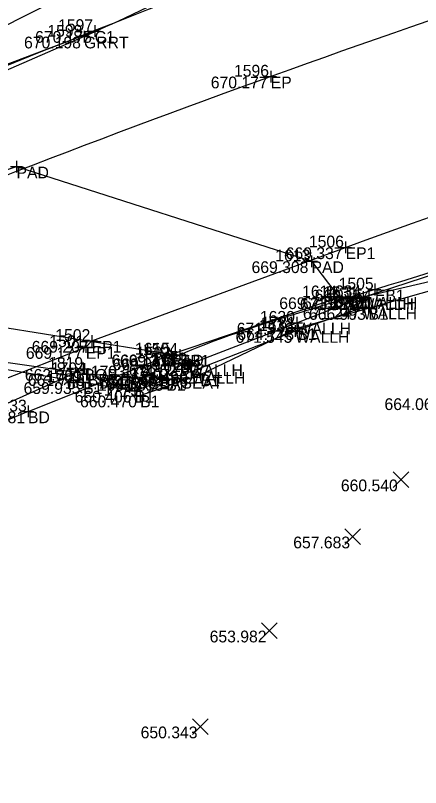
# Model space of a CAD drawing. Extents: x 2197382 to 2204062, y 634117 to 636522.
# Drawn here: x 2202998.7 to 2203033.1, y 635376.2 to 635441.9 of the extents above; entities that cross this region are included whole.
import ezdxf

# ---------------------------------------------------------------- set-up
doc = ezdxf.new("R2010")
doc.units = 0
for name, color, linetype in [('_CIVIL_CONSTRUCTION', 7, 'Continuous'), ('BR_P_Gen_Approach_Slab', 7, 'Continuous'), ('BR_X_SV_Beam_Seat', 7, 'Continuous'), ('BR_X_SV_Bottom_of_Beam', 7, 'Continuous'), ('BR_X_SV_Bottom_of_Beam_Text', 7, 'Continuous'), ('BR_X_SV_Deck_Top', 7, 'Continuous'), ('BR_X_SV_Deck_Top_Text', 7, 'Continuous'), ('BR_X_SV_Shot_Marker', 7, 'Continuous'), ('Default', 7, 'Continuous'), ('DR_X_Headwall', 7, 'Continuous'), ('GE_P_Alignment_100_Distances', 7, 'Continuous'), ('GE_X_Alignment', 7, 'Continuous'), ('PF_P_Grade_Line', 7, 'Continuous'), ('PV_X_Curb', 7, 'Continuous'), ('RD_X_GR_Rt', 7, 'Continuous'), ('RW_X_CL_100_Curve_Data', 7, 'Continuous'), ('SH_Border', 7, 'Continuous'), ('SH_Cut_Line', 7, 'Continuous'), ('SH_Data', 7, 'Continuous'), ('SH_Text', 7, 'Continuous')]:
    doc.layers.add(name, color=color, linetype=linetype)

msp = doc.modelspace()

# ---------------------------------------------------------------- linework, layer by layer
at = {"layer": '_CIVIL_CONSTRUCTION'}
for p, q in [((2203005.415, 635441.073), (2203005.415, 635440.073)), ((2203004.506, 635440.595), (2203004.506, 635439.595)), ((2203004.915, 635440.573), (2203005.915, 635440.573)), ((2203005.415, 635440.573), (2203005.415, 635440.573)), ((2203004.006, 635440.095), (2203005.006, 635440.095)), ((2203004.506, 635440.095), (2203004.506, 635440.095)), ((2203020.38, 635437.196), (2203020.38, 635436.196)), ((2203019.88, 635436.696), (2203020.88, 635436.696)), ((2203020.38, 635436.696), (2203020.38, 635436.696)), ((2202998.767, 635429.534), (2202998.767, 635428.534)), ((2202998.267, 635429.034), (2202999.267, 635429.034)), ((2202998.767, 635429.034), (2202998.767, 635429.034)), ((2203026.75, 635422.664), (2203026.75, 635421.664)), ((2203026.25, 635422.164), (2203027.25, 635422.164)), ((2203026.75, 635422.164), (2203026.75, 635422.164)), ((2203023.848, 635421.478), (2203023.848, 635420.478)), ((2203023.348, 635420.978), (2203024.348, 635420.978)), ((2203023.848, 635420.978), (2203023.848, 635420.978)), ((2203029.243, 635419.076), (2203029.243, 635418.076)), ((2203026.189, 635418.412), (2203026.189, 635417.412)), ((2203027.939, 635418.339), (2203027.939, 635417.339)), ((2203028.231, 635418.431), (2203028.231, 635417.431)), ((2203028.743, 635418.576), (2203029.743, 635418.576)), ((2203029.243, 635418.576), (2203029.243, 635418.576)), ((2203025.689, 635417.912), (2203026.689, 635417.912)), ((2203026.189, 635417.912), (2203026.189, 635417.912)), ((2203027.439, 635417.839), (2203028.439, 635417.839)), ((2203027.731, 635417.931), (2203028.731, 635417.931)), ((2203027.939, 635417.839), (2203027.939, 635417.839)), ((2203028.214, 635417.55), (2203028.214, 635416.55)), ((2203028.231, 635417.931), (2203028.231, 635417.931)), ((2203028.695, 635417.498), (2203028.695, 635416.498)), ((2203027.714, 635417.05), (2203028.714, 635417.05)), ((2203028.195, 635416.998), (2203029.195, 635416.998)), ((2203028.214, 635417.05), (2203028.214, 635417.05)), ((2203028.695, 635416.998), (2203028.695, 635416.998)), ((2203022.591, 635416.25), (2203022.591, 635415.25)), ((2203022.091, 635415.75), (2203023.091, 635415.75)), ((2203022.461, 635415.543), (2203022.461, 635414.543)), ((2203022.591, 635415.75), (2203022.591, 635415.75)), ((2203022.64, 635415.776), (2203022.64, 635414.776)), ((2203005.156, 635414.704), (2203005.156, 635413.704)), ((2203021.961, 635415.043), (2203022.961, 635415.043)), ((2203022.14, 635415.276), (2203023.14, 635415.276)), ((2203022.461, 635415.043), (2203022.461, 635415.043)), ((2203022.64, 635415.276), (2203022.64, 635415.276)), ((2203004.654, 635414.181), (2203004.654, 635413.181)), ((2203004.656, 635414.204), (2203005.656, 635414.204)), ((2203005.156, 635414.204), (2203005.156, 635414.204)), ((2203004.154, 635413.681), (2203005.154, 635413.681)), ((2203004.654, 635413.681), (2203004.654, 635413.681)), ((2203011.925, 635413.541), (2203011.925, 635412.541)), ((2203012.655, 635413.513), (2203012.655, 635412.513)), ((2203011.425, 635413.041), (2203012.425, 635413.041)), ((2203011.925, 635413.041), (2203011.925, 635413.041)), ((2203012.015, 635413.219), (2203012.015, 635412.219)), ((2203012.155, 635413.013), (2203013.155, 635413.013)), ((2203012.655, 635413.013), (2203012.655, 635413.013)), ((2203004.554, 635412.314), (2203004.554, 635411.314)), ((2203011.515, 635412.719), (2203012.515, 635412.719)), ((2203012.015, 635412.719), (2203012.015, 635412.719)), ((2203012.897, 635412.206), (2203013.897, 635412.206)), ((2203013.397, 635412.706), (2203013.397, 635411.706)), ((2203013.397, 635412.206), (2203013.397, 635412.206)), ((2203004.054, 635411.814), (2203005.054, 635411.814)), ((2203004.554, 635411.814), (2203004.554, 635411.814)), ((2203011.512, 635411.463), (2203011.512, 635410.463)), ((2203013.114, 635411.565), (2203014.114, 635411.565)), ((2203013.614, 635412.065), (2203013.614, 635411.065)), ((2203013.614, 635411.565), (2203013.614, 635411.565)), ((2203014.402, 635411.844), (2203014.402, 635410.844)), ((2203004.435, 635411.191), (2203004.435, 635410.191)), ((2203011.012, 635410.963), (2203012.012, 635410.963)), ((2203011.512, 635410.963), (2203011.512, 635410.963)), ((2203013.902, 635411.344), (2203014.902, 635411.344)), ((2203014.402, 635411.344), (2203014.402, 635411.344)), ((2203003.935, 635410.691), (2203004.935, 635410.691)), ((2203004.435, 635410.691), (2203004.435, 635410.691)), ((2203008.816, 635410.46), (2203008.816, 635409.46)), ((2203008.316, 635409.96), (2203009.316, 635409.96)), ((2203008.78, 635409.551), (2203009.78, 635409.551)), ((2203008.816, 635409.96), (2203008.816, 635409.96)), ((2203009.28, 635410.051), (2203009.28, 635409.051)), ((2203009.28, 635409.551), (2203009.28, 635409.551)), ((2202999.242, 635408.201), (2203000.242, 635408.201)), ((2202999.742, 635408.701), (2202999.742, 635407.701)), ((2202999.742, 635408.201), (2202999.742, 635408.201))]:
    msp.add_line(p, q, dxfattribs=at)
at = {"layer": 'BR_P_Gen_Approach_Slab'}
msp.add_lwpolyline([(2202961.037, 635421.211), (2202992.345, 635433.447), (2202995.802, 635428.045), (2202998.767, 635429.034), (2203023.848, 635420.978), (2203026.189, 635417.912), (2203011.925, 635413.041)], close=True, dxfattribs=at)
at = {"layer": 'BR_X_SV_Bottom_of_Beam'}
msp.add_lwpolyline([(2203004.554, 635411.814), (2202987.707, 635404.283), (2202970.923, 635396.976), (2202953.857, 635390.063), (2202937.114, 635382.149)], dxfattribs=at)
at = {"layer": 'BR_X_SV_Deck_Top'}
for q in [(2203011.925, 635413.041), (2202923.181, 635376.197)]:
    msp.add_line((2202999.742, 635408.201), q, dxfattribs=at)
at = {"layer": 'BR_X_SV_Shot_Marker'}
for p, q in [((2203004.829, 635411.876), (2203004.829, 635410.876)), ((2203008.169, 635411.593), (2203008.169, 635410.593)), ((2203010.93, 635411.648), (2203010.93, 635410.648)), ((2203004.329, 635411.376), (2203005.329, 635411.376)), ((2203004.829, 635411.376), (2203004.829, 635411.376)), ((2203007.669, 635411.093), (2203008.669, 635411.093)), ((2203008.169, 635411.093), (2203008.169, 635411.093)), ((2203010.43, 635411.148), (2203011.43, 635411.148)), ((2203010.93, 635411.148), (2203010.93, 635411.148))]:
    msp.add_line(p, q, dxfattribs=at)
at = {"layer": 'Default'}
msp.add_lwpolyline([(2203010.93, 635411.148), (2203008.169, 635411.093), (2203004.829, 635411.376), (2202991.262, 635413.289), (2202991.069, 635413.101), (2202976.24, 635415.493), (2202976.127, 635415.526), (2202961.376, 635417.927), (2202961.247, 635417.936), (2202955.257, 635418.901), (2202955.015, 635419.365), (2202958.181, 635420.848)], dxfattribs=at)
at = {"layer": 'DR_X_Headwall'}
for points in [[(2203028.231, 635417.931), (2203039.816, 635421.698), (2203041.345, 635421.885), (2203041.59, 635421.173), (2203040.06, 635420.674)], [(2203013.614, 635411.565), (2203013.397, 635412.206), (2203022.591, 635415.75), (2203027.939, 635417.839), (2203028.214, 635417.05), (2203022.461, 635415.043)]]:
    msp.add_lwpolyline(points, close=True, dxfattribs=at)
at = {"layer": 'GE_P_Alignment_100_Distances'}
for p, q in [((2203005.156, 635414.204), (2203026.75, 635422.164)), ((2203004.654, 635413.681), (2203005.156, 635414.204)), ((2202973.99, 635401.58), (2203004.654, 635413.681))]:
    msp.add_line(p, q, dxfattribs=at)
for points in [[(2203509.325, 635523.639), (2203492.709, 635523.635), (2203459.449, 635522.771), (2203409.618, 635520.273), (2203359.906, 635516.085), (2203310.487, 635509.396), (2203261.113, 635501.99), (2203212.046, 635492.428), (2203163.488, 635480.651), (2203115.287, 635467.725), (2203067.636, 635452.84), (2203020.399, 635437.148), (2202989.518, 635425.126), (2202974.268, 635418.841)], [(2203026.75, 635422.164), (2203041.875, 635427.739), (2203072.979, 635437.38), (2203119.81, 635452.49), (2203167.644, 635464.687), (2203215.6, 635476.186), (2203263.862, 635485.772), (2203312.689, 635493.217), (2203361.79, 635499.124), (2203411.114, 635503.522), (2203460.348, 635505.942), (2203493.138, 635506.785), (2203509.372, 635506.858)]]:
    msp.add_open_spline(points, degree=3, dxfattribs=at)
at = {"layer": 'GE_X_Alignment'}
msp.add_line((2203012.015, 635412.719), (2203012.655, 635413.013), dxfattribs=at)
for points in [[(2203509.052, 635533.635), (2203492.463, 635533.632), (2203459.115, 635532.727), (2203409.096, 635530.449), (2203358.983, 635525.688), (2203309.163, 635519.456), (2203259.639, 635511.376), (2203210.257, 635501.873), (2203160.945, 635490.686), (2203112.434, 635476.962), (2203063.465, 635464.847), (2203018.457, 635445.242), (2202987.961, 635434.054), (2202973.986, 635427.145)], [(2203012.655, 635413.013), (2203017.915, 635415.429), (2203038.998, 635420.898), (2203074.314, 635435.088), (2203121.354, 635447.886), (2203168.652, 635461.375), (2203216.374, 635472.836), (2203264.58, 635481.881), (2203313.279, 635489.496), (2203362.166, 635495.909), (2203411.483, 635500.018), (2203460.323, 635502.299), (2203492.764, 635503.649), (2203508.722, 635503.638)]]:
    msp.add_open_spline(points, degree=3, dxfattribs=at)
at = {"layer": 'PF_P_Grade_Line'}
msp.add_lwpolyline([(2203905.242, 635544.116), (2203857.352, 635543.047), (2203808.123, 635540.236), (2203758.647, 635537.754), (2203707.868, 635536.993), (2203658.673, 635537.689), (2203608.571, 635538.61), (2203557.914, 635538.188), (2203508.63, 635537.596), (2203457.137, 635535.791), (2203407.798, 635532.16), (2203358.092, 635527.848), (2203307.62, 635521.361), (2203257.609, 635512.38), (2203209.518, 635502.636), (2203160.694, 635490.379), (2203110.741, 635480.717), (2203062.695, 635468.061), (2203015.531, 635449.981), (2202971.299, 635427.613)], dxfattribs=at)
at = {"layer": 'PV_X_Curb'}
msp.add_lwpolyline([(2203005.415, 635440.573), (2202996.73, 635437.281), (2202986.966, 635433.003), (2202986.518, 635432.892)], dxfattribs=at)
at = {"layer": 'RD_X_GR_Rt'}
msp.add_line((2203004.506, 635440.095), (2202984.33, 635431.381), dxfattribs=at)
msp.add_open_spline([(2203111.903, 635478.773), (2203095.805, 635474.299), (2203063.972, 635464.196), (2203027.87, 635451.622), (2203008.766, 635441.935), (2203004.506, 635440.095)], degree=3, dxfattribs=at)
at = {"layer": 'RW_X_CL_100_Curve_Data'}
for p, q in [((2203030.792, 635401.74), (2203032.126, 635403.076)), ((2203030.792, 635403.076), (2203032.126, 635401.74)), ((2203026.69, 635396.884), (2203028.024, 635398.22)), ((2203026.69, 635398.22), (2203028.024, 635396.884)), ((2203019.594, 635388.882), (2203020.928, 635390.218)), ((2203019.594, 635390.218), (2203020.928, 635388.882)), ((2203013.716, 635380.721), (2203015.05, 635382.056)), ((2203013.716, 635382.056), (2203015.05, 635380.721))]:
    msp.add_line(p, q, dxfattribs=at)
at = {"layer": 'SH_Text'}
for points in [[(2203009.28, 635409.551), (2203014.402, 635411.344), (2203022.64, 635415.276), (2203028.695, 635416.998), (2203041.939, 635420.771), (2203041.34, 635421.924)], [(2202954.272, 635420.101), (2202955.118, 635418.714), (2202976.011, 635415.318), (2202990.948, 635412.92), (2203004.435, 635410.691), (2203008.816, 635409.96), (2203011.512, 635410.963)]]:
    msp.add_lwpolyline(points, dxfattribs=at)

# ---------------------------------------------------------------- texts
at = {"layer": 'BR_X_SV_Beam_Seat'}
for s, p in [('1794', (2203001.688, 635411.376)), ('1793', (2203005.086, 635411.093)), ('1792', (2203007.838, 635411.148)), ('661.748', (2202999.729, 635410.376)), ('661.704', (2203003.047, 635410.093)), ('BRSEAT', (2203004.829, 635410.376)), ('661.680', (2203005.816, 635410.148)), ('BRSEAT', (2203008.169, 635410.093)), ('BRSEAT', (2203010.93, 635410.148))]:
    msp.add_text(s, height=1, dxfattribs=at).set_placement(p)
at = {"layer": 'BR_X_SV_Bottom_of_Beam_Text'}
for s, p in [('1819', (2203001.452, 635411.814)), ('662.661', (2202999.472, 635410.814)), ('BOB', (2203004.554, 635410.814))]:
    msp.add_text(s, height=1, dxfattribs=at).set_placement(p)
at = {"layer": 'BR_X_SV_Deck_Top_Text'}
for s, p in [('2233', (2202996.659, 635408.201)), ('668.981', (2202994.66, 635407.201)), ('BD', (2202999.742, 635407.201))]:
    msp.add_text(s, height=1, dxfattribs=at).set_placement(p)
at = {"layer": 'SH_Border'}
for s, p in [('C1', (2203005.415, 635439.573)), ('GRRT', (2203004.506, 635439.095)), ('EP', (2203020.38, 635435.696)), ('PAD', (2202998.767, 635428.034)), ('EP1', (2203026.75, 635421.164)), ('PAD', (2203023.848, 635419.978)), ('EB1', (2203029.243, 635417.576)), ('PAD', (2203026.189, 635416.912)), ('WALLH', (2203027.939, 635416.839)), ('WALLH', (2203028.231, 635416.931)), ('WALLH', (2203028.214, 635416.05)), ('B1', (2203028.695, 635415.998)), ('WALLH', (2203022.591, 635414.75)), ('WALLH', (2203022.461, 635414.043)), ('B1', (2203022.64, 635414.276)), ('EP1', (2203005.156, 635413.204)), ('EP1', (2203004.654, 635412.681)), ('PAD', (2203011.925, 635412.041)), ('EB1', (2203012.655, 635412.013)), ('EB1', (2203012.015, 635411.719)), ('WALLH', (2203013.397, 635411.206)), ('WALLH', (2203013.614, 635410.565)), ('B1', (2203011.512, 635409.963)), ('B1', (2203014.402, 635410.344)), ('B1', (2203004.435, 635409.691)), ('B1', (2203008.816, 635408.96)), ('B1', (2203009.28, 635408.551))]:
    msp.add_text(s, height=1, dxfattribs=at).set_placement(p)
at = {"layer": 'SH_Cut_Line'}
for s, p in [('1598', (2203001.387, 635440.095)), ('1597', (2203002.3, 635440.573)), ('1596', (2203017.257, 635436.696)), ('1506', (2203023.627, 635422.164)), ('1613', (2203020.765, 635420.978)), ('1505', (2203026.154, 635418.576)), ('1614', (2203023.048, 635417.912)), ('1631', (2203024.839, 635417.839)), ('1634', (2203025.09, 635417.931)), ('1632', (2203025.122, 635417.05)), ('1782', (2203025.603, 635416.998)), ('1630', (2203019.459, 635415.75)), ('1633', (2203019.378, 635415.043)), ('1781', (2203019.54, 635415.276)), ('1502', (2203002.064, 635414.204)), ('1501', (2203001.554, 635413.681)), ('1615', (2203008.836, 635413.041)), ('1503', (2203008.932, 635412.719)), ('1504', (2203009.514, 635413.013)), ('1629', (2203010.295, 635412.206)), ('1628', (2203010.495, 635411.565)), ('1780', (2203011.27, 635411.344)), ('1789', (2203001.333, 635410.691)), ('1791', (2203008.412, 635410.963)), ('1790', (2203005.684, 635409.96)), ('1779', (2203006.178, 635409.551))]:
    msp.add_text(s, height=1, dxfattribs=at).set_placement(p)
at = {"layer": 'SH_Data'}
for s, p in [('670.175', (2203000.345, 635439.573)), ('670.198', (2202999.406, 635439.095)), ('670.177', (2203015.284, 635435.696)), ('669.337', (2203021.654, 635421.164)), ('669.308', (2203018.748, 635419.978)), ('669.154', (2203024.121, 635417.576)), ('669.239', (2203021.105, 635416.912)), ('671.281', (2203022.857, 635416.839)), ('671.696', (2203023.127, 635416.931)), ('671.247', (2203023.118, 635416.05)), ('666.993', (2203023.631, 635415.998)), ('671.546', (2203017.487, 635414.75)), ('671.545', (2203017.391, 635414.043)), ('664.778', (2203017.54, 635414.276)), ('669.207', (2203000.06, 635413.204)), ('669.177', (2202999.558, 635412.681)), ('669.131', (2203006.843, 635412.041)), ('669.091', (2203006.933, 635411.719)), ('669.178', (2203007.555, 635412.013)), ('671.521', (2203008.315, 635411.206)), ('671.490', (2203008.5, 635410.565)), ('660.818', (2203006.412, 635409.963)), ('661.884', (2203009.28, 635410.344)), ('659.935', (2202999.365, 635409.691)), ('660.406', (2203003.712, 635408.96)), ('660.470', (2203004.166, 635408.551)), ('664.069', (2203030.053, 635408.322)), ('660.540', (2203026.345, 635401.408)), ('657.683', (2203022.293, 635396.552)), ('653.982', (2203015.188, 635388.55)), ('650.343', (2203009.319, 635380.389))]:
    msp.add_text(s, height=1, dxfattribs=at).set_placement(p)

doc.saveas('drawing.dxf')
